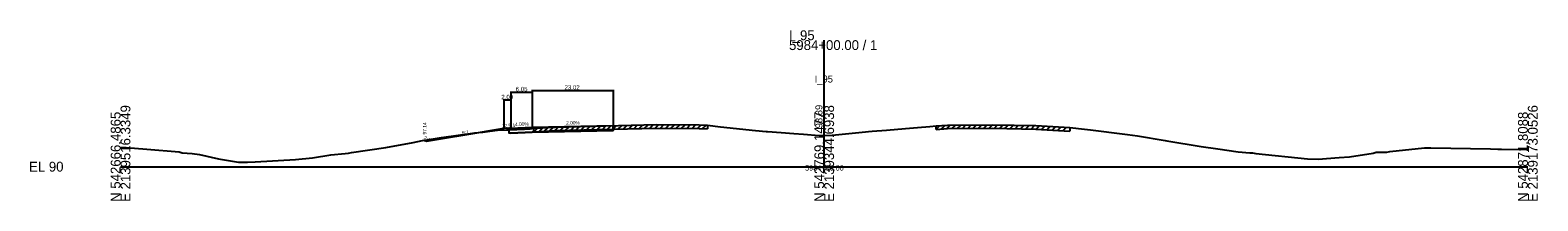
# Model space of a CAD drawing. Extents: x -12534 to 3403, y -1332 to 21983.
# Drawn here: x -25.7 to 402.8, y 15490.3 to 15538.8 of the extents above; entities that cross this region are included whole.
import ezdxf

# ---------------------------------------------------------------- set-up
doc = ezdxf.new("R2010")
doc.units = 0
for name, color, linetype in [('RD_GPK_XS_Cell', 7, 'Continuous'), ('RD_XD_TX_Width', 7, 'Continuous'), ('RD_XS_Base', 7, 'Continuous'), ('RD_XS_EarthShd', 7, 'Continuous'), ('RD_XS_EwShp', 7, 'Continuous'), ('RD_XS_ExGround', 7, 'Continuous'), ('RD_XS_ExPaveRet', 7, 'Continuous'), ('RD_XS_OSBase', 7, 'Continuous'), ('RD_XS_Pave', 7, 'Continuous'), ('RD_XS_TieSlope', 7, 'Continuous'), ('RD_XS_TX_Baseline', 7, 'Continuous'), ('RD_XS_TX_Elev_EX', 7, 'Continuous'), ('RD_XS_TX_Elev_PR', 7, 'Continuous'), ('RD_XS_TX_ShdSlope', 7, 'Continuous'), ('RD_XS_TX_Slope', 7, 'Continuous'), ('RD_XS_TX_Station', 7, 'Continuous')]:
    doc.layers.add(name, color=color, linetype=linetype)

msp = doc.modelspace()

# ---------------------------------------------------------------- linework, layer by layer
at = {"layer": 'RD_GPK_XS_Cell'}
for p, q in [((200, 15500), (200, 15535.92)), ((0, 15500), (200, 15500)), ((200, 15500), (400, 15500))]:
    msp.add_line(p, q, dxfattribs=at)
at = {"layer": 'RD_XD_TX_Width'}
for p, q in [((116.98, 15521.82), (116.98, 15511.41)), ((116.98, 15521.62), (140, 15521.62)), ((140, 15521.82), (140, 15511.87)), ((108.93, 15519.11), (108.93, 15511)), ((110.93, 15518.91), (108.93, 15518.91)), ((110.93, 15521.36), (110.93, 15511.16)), ((110.93, 15521.16), (116.98, 15521.16)), ((110.93, 15519.11), (110.93, 15511.16)), ((116.98, 15521.36), (116.98, 15511.41))]:
    msp.add_line(p, q, dxfattribs=at)
at = {"layer": 'RD_XS_Base'}
for p, q in [((110.93, 15509.56), (116.98, 15509.81)), ((116.98, 15509.81), (140, 15510.27))]:
    msp.add_line(p, q, dxfattribs=at)
at = {"layer": 'RD_XS_EarthShd'}
msp.add_line((110.93, 15510.96), (108.93, 15510.8), dxfattribs=at)
at = {"layer": 'RD_XS_EwShp'}
for points in [[(91.21, 15508.32), (100.67, 15509.57), (103, 15509.81), (86.93, 15507.14), (86.26, 15507.47)], [(110.43, 15510.5), (110.43, 15510.54), (110.93, 15510.56), (110.93, 15510.96), (108.93, 15510.8), (103, 15509.81), (104.26, 15509.95), (107.11, 15510.36)], [(110.93, 15509.56), (110.43, 15509.54), (110.43, 15510.5), (114.78, 15510.68), (116.43, 15510.76), (117.45, 15510.89), (123.39, 15511.26), (140, 15511.67), (140, 15511.27), (140, 15510.27), (116.98, 15509.81)]]:
    msp.add_lwpolyline(points, close=True, dxfattribs=at)
at = {"layer": 'RD_XS_ExGround'}
msp.add_lwpolyline([(0, 15505.47), (1.55, 15505.45), (7.43, 15504.98), (16.7, 15504.21), (17.56, 15503.94), (20.35, 15503.74), (22.4, 15503.42), (27.8, 15502.21), (33.48, 15501.31), (36.05, 15501.31), (38.24, 15501.38), (49.76, 15502.03), (54.55, 15502.54), (59.73, 15503.36), (63.81, 15503.77), (64.8, 15503.84), (65.6, 15503.98), (75.4, 15505.48), (83.21, 15506.88), (85.85, 15507.4), (91.21, 15508.32), (100.67, 15509.57), (104.26, 15509.95), (107.11, 15510.36), (114.78, 15510.68), (116.43, 15510.76), (117.45, 15510.89), (123.39, 15511.26), (152.38, 15511.97), (164.48, 15511.84), (166.81, 15511.76), (170.53, 15511.29), (180.48, 15510.26), (183.5, 15510.02), (183.87, 15510.01), (187.8, 15509.7), (191.35, 15509.43), (194.11, 15509.21), (198.61, 15508.88), (200, 15508.89), (202.25, 15508.94), (211.72, 15509.94), (212.57, 15509.95), (213.6, 15510.07), (217.7, 15510.38), (223.12, 15510.83), (226.52, 15511.12), (229.99, 15511.45), (231.78, 15511.59), (235.08, 15511.8), (247.81, 15511.89), (260.18, 15511.65), (269.85, 15511.11), (273.99, 15510.67), (275.72, 15510.46), (278.68, 15510.1), (282.44, 15509.62), (286.18, 15509.14), (289.01, 15508.73), (296.91, 15507.43), (297.38, 15507.35), (307.17, 15505.76), (311.86, 15505.06), (317.67, 15504.25), (321.01, 15503.95), (321.77, 15503.91), (322.66, 15503.79), (337.34, 15502.25), (340.43, 15502.12), (346.33, 15502.64), (349.26, 15502.82), (356.01, 15503.87), (356.84, 15504.11), (358.86, 15504.11), (359.9, 15504.16), (360.81, 15504.27), (370.6, 15505.35), (372.41, 15505.31), (389.37, 15505.03), (391.44, 15504.99), (392.52, 15504.98), (399.69, 15504.85), (400, 15504.84)], dxfattribs=at)
at = {"layer": 'RD_XS_ExPaveRet'}
for p, q in [((117.45, 15509.89), (118.52, 15510.96)), ((117.45, 15509.89), (117.45, 15510.89)), ((117.45, 15509.89), (123.39, 15510.26)), ((118.95, 15509.99), (120.02, 15511.05)), ((120.45, 15510.08), (121.52, 15511.14)), ((121.95, 15510.17), (123.02, 15511.24)), ((123.39, 15510.26), (152.38, 15510.97)), ((123.45, 15510.26), (124.48, 15511.29)), ((124.95, 15510.3), (125.98, 15511.32)), ((126.45, 15510.33), (127.48, 15511.36)), ((127.95, 15510.37), (128.98, 15511.4)), ((129.45, 15510.41), (130.48, 15511.43)), ((130.95, 15510.45), (131.98, 15511.47)), ((132.45, 15510.48), (133.48, 15511.51)), ((133.95, 15510.52), (134.98, 15511.54)), ((135.45, 15510.56), (136.48, 15511.58)), ((136.95, 15510.59), (137.98, 15511.62)), ((138.45, 15510.63), (139.48, 15511.65)), ((139.95, 15510.67), (140.98, 15511.69)), ((141.45, 15510.7), (142.48, 15511.73)), ((142.95, 15510.74), (143.98, 15511.77)), ((144.45, 15510.78), (145.48, 15511.8)), ((145.95, 15510.81), (146.98, 15511.84)), ((147.45, 15510.85), (148.48, 15511.88)), ((148.95, 15510.89), (149.98, 15511.91)), ((150.45, 15510.92), (151.48, 15511.95)), ((151.95, 15510.96), (152.96, 15511.97)), ((152.38, 15510.97), (164.48, 15510.84)), ((153.45, 15510.96), (154.44, 15511.95)), ((154.95, 15510.94), (155.94, 15511.93)), ((156.45, 15510.93), (157.44, 15511.92)), ((157.95, 15510.91), (158.94, 15511.9)), ((159.45, 15510.9), (160.44, 15511.89)), ((160.95, 15510.88), (161.94, 15511.87)), ((162.45, 15510.86), (163.44, 15511.85)), ((163.95, 15510.85), (164.93, 15511.83)), ((164.48, 15510.84), (166.81, 15510.76)), ((165.45, 15510.81), (166.42, 15511.78)), ((166.81, 15511.76), (166.81, 15510.76)), ((231.78, 15510.59), (232.85, 15511.66)), ((231.78, 15510.59), (231.78, 15511.59)), ((231.78, 15510.59), (235.08, 15510.8)), ((233.28, 15510.69), (234.35, 15511.76)), ((234.78, 15510.79), (235.8, 15511.81)), ((235.08, 15510.8), (247.81, 15510.89)), ((236.28, 15510.81), (237.29, 15511.82)), ((237.78, 15510.82), (238.79, 15511.83)), ((239.28, 15510.83), (240.29, 15511.84)), ((240.78, 15510.84), (241.79, 15511.85)), ((242.28, 15510.85), (243.29, 15511.86)), ((243.78, 15510.86), (244.79, 15511.87)), ((245.28, 15510.87), (246.29, 15511.88)), ((246.78, 15510.88), (247.79, 15511.89)), ((247.81, 15510.89), (260.18, 15510.65)), ((248.28, 15510.88), (249.26, 15511.86)), ((249.78, 15510.85), (250.76, 15511.83)), ((251.28, 15510.82), (252.26, 15511.8)), ((252.78, 15510.79), (253.76, 15511.78)), ((254.28, 15510.77), (255.26, 15511.75)), ((255.78, 15510.74), (256.76, 15511.72)), ((257.28, 15510.71), (258.26, 15511.69)), ((258.78, 15510.68), (259.76, 15511.66)), ((260.18, 15510.65), (269.85, 15510.11)), ((260.28, 15510.65), (261.23, 15511.59)), ((261.78, 15510.56), (262.73, 15511.51)), ((263.28, 15510.48), (264.23, 15511.42)), ((264.78, 15510.39), (265.73, 15511.34)), ((266.28, 15510.31), (267.23, 15511.26)), ((267.78, 15510.22), (268.73, 15511.17)), ((269.85, 15511.11), (269.85, 15510.11))]:
    msp.add_line(p, q, dxfattribs=at)
at = {"layer": 'RD_XS_OSBase'}
for p, q in [((110.43, 15510.54), (110.93, 15510.56)), ((110.43, 15509.54), (110.43, 15510.54)), ((110.93, 15509.56), (110.43, 15509.54)), ((110.93, 15510.56), (110.93, 15510.96)), ((140, 15511.27), (140, 15511.67)), ((140, 15510.27), (140, 15511.27))]:
    msp.add_line(p, q, dxfattribs=at)
at = {"layer": 'RD_XS_Pave'}
for p, q in [((110.93, 15510.96), (116.98, 15511.21)), ((116.98, 15511.21), (140, 15511.67))]:
    msp.add_line(p, q, dxfattribs=at)
at = {"layer": 'RD_XS_TieSlope'}
for p, q in [((108.93, 15510.8), (86.93, 15507.14)), ((86.93, 15507.14), (86.26, 15507.47))]:
    msp.add_line(p, q, dxfattribs=at)

# ---------------------------------------------------------------- texts
at = {"layer": 'RD_GPK_XS_Cell'}
for s, p in [('I_95', (190, 15535.92)), ('5984+00.00 / 1', (190, 15533.12)), ('EL 90', (-26, 15498.6))]:
    msp.add_text(s, height=2.8, dxfattribs=at).set_placement(p)
for s, p in [('E 2139516.3349', (2.8, 15490)), ('E 2139344.6938', (202.8, 15490)), ('E 2139173.0526', (402.8, 15490)), ('N 542666.4865', (0, 15490)), ('N 542769.1477', (200, 15490)), ('N 542871.8088', (400, 15490))]:
    msp.add_text(s, height=2.8, rotation=90, dxfattribs=at).set_placement(p)
at = {"layer": 'RD_XD_TX_Width'}
for s, p in [('6.05', (112.31, 15521.41)), ('23.02', (126.19, 15521.87)), ('2.00', (108.24, 15519.16))]:
    msp.add_text(s, height=1.25, dxfattribs=at).set_placement(p)
at = {"layer": 'RD_XS_TX_Baseline'}
msp.add_text('I_95', height=2, dxfattribs=at).set_placement((197.28, 15523.89))
at = {"layer": 'RD_XS_TX_Elev_EX'}
msp.add_text('98.89', height=2, rotation=90, dxfattribs=at).set_placement((199.5, 15510.89))
at = {"layer": 'RD_XS_TX_Elev_PR'}
msp.add_text('97.14', height=1, rotation=90, dxfattribs=at).set_placement((86.93, 15509.14))
at = {"layer": 'RD_XS_TX_ShdSlope'}
msp.add_text('12.5:1', height=1, rotation=4.5739, dxfattribs=at).set_placement((108.4, 15511.01))
msp.add_text('12.5:1', height=1, rotation=4.5739, dxfattribs=at).set_placement((108.4, 15511.01))
at = {"layer": 'RD_XS_TX_Slope'}
for s, rotation, p in [('2.00%', 1.1458, (126.63, 15511.9)), ('2:1', 333.4349, (86.04, 15507.86)), ('6:1', 9.4623, (97.2, 15509.1)), ('4.00%', 2.2906, (112.14, 15511.51))]:
    msp.add_text(s, height=1, rotation=rotation, dxfattribs=at).set_placement(p)
at = {"layer": 'RD_XS_TX_Station'}
msp.add_text('5984+00.00', height=1.5, dxfattribs=at).set_placement((194.56, 15498.89))

doc.saveas('drawing.dxf')
